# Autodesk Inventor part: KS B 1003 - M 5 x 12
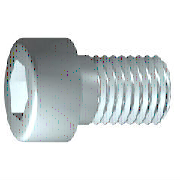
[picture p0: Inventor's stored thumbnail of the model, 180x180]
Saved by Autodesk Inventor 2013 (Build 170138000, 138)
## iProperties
IsCustomPart: 0
Created: 2009-02
Part Number: KS B 1003 - M 5 x 12
Material: 강, 연강
Description: 6각머리 태핑 나사
Document SubType Name: Modeling
Standard: KS B 1003
Designer: KYOUNG IL JANG
Standards Organization: KS
Language: ko-KR
Size Designation: M 5 x 12
Categories: <MemberInstance><Categories><Category DisplayName="조임쇠" InternalName="e4da775c-781d-43d5-af7c-5136215cf5a6" Mnemonic="FSTN"><Category DisplayName="볼트" InternalN
Density: 7.86 g/cm^3
Mass: 3.72825 g
Surface Area: 4.62573 cm^2
Volume: 0.474332 cm^3
Author: KYOUNG IL JANG
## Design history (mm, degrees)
sketch "스케치1"
  geometry: L1 (-1.167, 0)-(12, 0); L2 (12, 0)-(12, 2.5); L3 (12, 2.5)-(2, 2.5); L4 (2, 2.5)-(1.509, 2.5); L5 (1.509, 2.5)-(0, 2.5); L6 (0, 2.5)-(0, 4.25); L7 (0, 4.25)-(-5, 4.25); L8 (-5, 4.25)-(-5, 2.309); L9 (-5, 2.309)-(-2.5, 2.309); L10 (-2.5, 2.309)-(-1.167, 0); L11 (-8.4, 0)-(15.4, 0) reference; L12 (0, -0.85)-(0, 5.1) reference; L13 (2, 2.5)-(0, 2.5)
  constraints: 22 end point, 6 parallel, 2 collinear, 2 perpendicular, 1 horizontal, 1 point on line
  dimensions: "d1" = 10 distance from line of L3.end L2 (= GEL); "d2" = 0.49086 distance of L4.end L3.end (computed from GAL); "d3" = 5 distance between parallel lines of L8 L6 (= KOH); "d4" = 2.5 distance of L8.end L9.end (= INTI); "d5" = 60 deg angle of L10 L1; "d6" = 5 diameter of L3 L1 (= GD); "d7" = 5 diameter of L5 L1 (= BDM); "d8" = 4.6188 diameter of L9 L1 (= 1.1547 x SW); "d9" = 8.5 diameter of L7 L1 (= KOD); "d26" = 12 distance between parallel lines of L12 L2 (= NLG)
revolve "본체" sketch "스케치1" stored, may be unused: angle "d10" = 90 deg
sketch "스케치2"
  geometry: L1 (0, -5.95)-(0, 5.95) reference; L2 (-5.95, 0)-(5.95, 0) reference; L3 (2.309, 0)-(1.155, -2); L4 (1.155, -2)-(-1.155, -2); L5 (-1.155, -2)-(-2.309, 0); L6 (-2.309, 0)-(-1.155, 2); L7 (-1.155, 2)-(1.155, 2); L8 (1.155, 2)-(2.309, 0); 2 further points
  constraints: 12 end point, 1 coincident, 1 horizontal alignment, 1 point on line, 12 other
extrude "슬롯" join sketch "스케치2" stored distance "d11" = 10; taper "d12" = 0 deg
workplane "Work Plane1"
fillet "Fillet2" dims "d30" = 0.1 (= R)
body "Solid1"
fillet "모깎기1" dims "d17" = 0.5 (= RR)
feature "스레드" dims "d13" = 10 (= GEL), "d14" = 0
chamfer "모따기1" distance "d15" = 0.49076 (= -0.5 x SPD + 0.5 x GD); stored, may be unused: second distance "d16" = 0.49076 (= GUL), angle "d27" = 45 deg
other parameters: "GD" = 5 (= NND) [user parameter; used in 2 equation terms], "NLG" = 12 [user parameter; used in 1 equation term], "GEL" = 10 [user parameter; used in 2 equation terms], "KOD" = 8.5 [user parameter; used in 1 equation term], "KOH" = 5 [user parameter; used in 1 equation term], "INTI" = 2.5 [user parameter; used in 1 equation term], "GAL" = 0.49076 (= 0.61345 x PTC) [user parameter; used in 1 equation term], "GUL" = 0.49076 (= 0.61345 x PTC) [user parameter; used in 1 equation term], "BDM" = 5 (= NND) [user parameter; used in 1 equation term], "SW" = 4 [user parameter; used in 2 equation terms], "RR" = 0.5 [user parameter; used in 1 equation term], "SPD" = 4.01848 (= NND - 1.2269 x PTC) [user parameter; used in 1 equation term], "d19" = 0, "d28" = 0, "d29" = 0, "R" = 0.1 [user parameter; used in 1 equation term], "PHH" = 0.2 [user parameter], "GD1" = 4.01848 (= THREADDIA - 1.2269 x PTC) [user parameter], "THREADDIA" = 5 [user parameter; used in 1 equation term], "FAWI" = 45 deg [user parameter], "TPU" = 12.5 (computed from PTC) [user parameter], "PTC" = 0.8 [user parameter; used in 5 equation terms], "NND" = 5 [user parameter; used in 3 equation terms], "TOA" = 30 deg [user parameter], "E0" = 4.62 (= 1.155 x SW) [user parameter]
